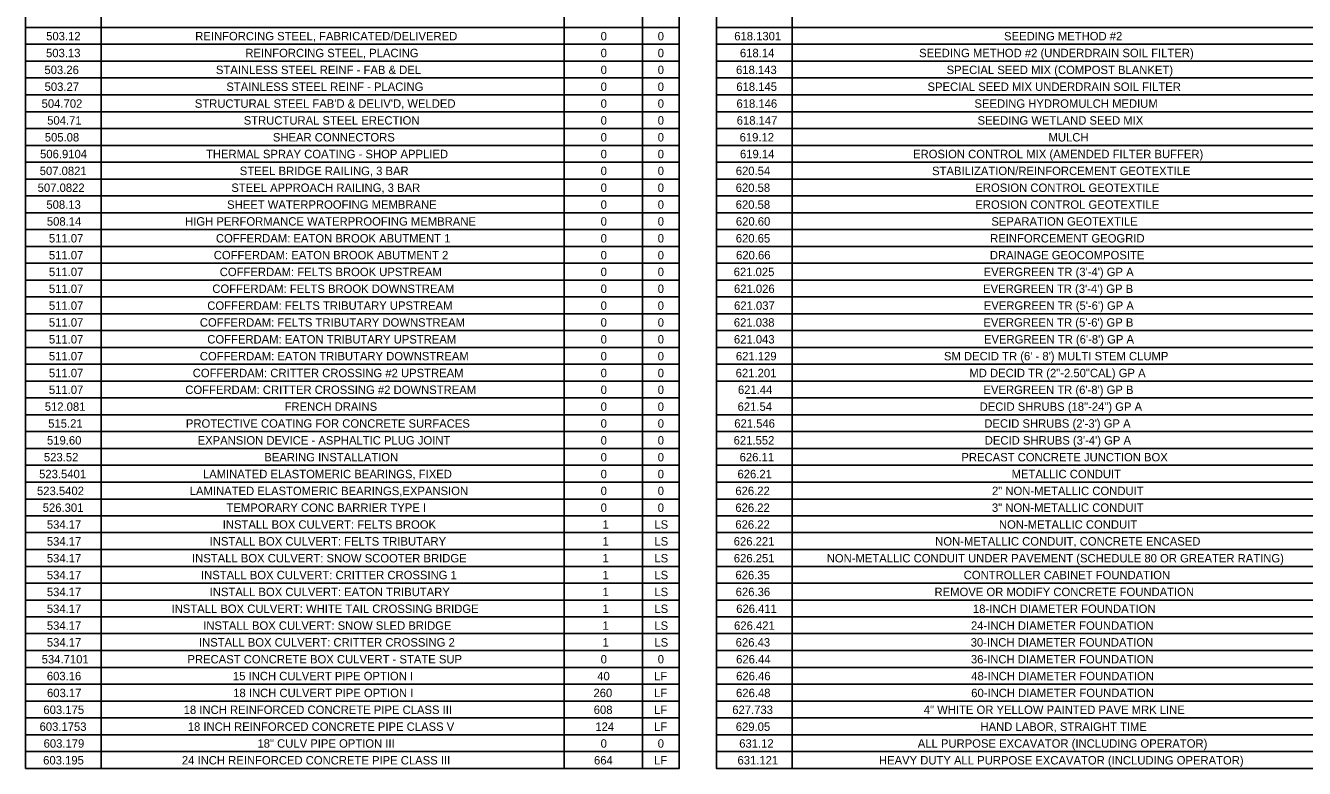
# Model space of a CAD drawing. Extents: x -18.7 to 5.6, y -2.7 to 4.
# Drawn here: x 3.137 to 4.632, y 0.019 to 0.887 of the extents above; entities that cross this region are included whole.
import ezdxf

# ---------------------------------------------------------------- set-up
doc = ezdxf.new("R2010")
doc.units = 0
doc.layers.add('ANNOTATION', color=7, linetype='Continuous')
doc.layers.add('BORDER', color=7, linetype='Continuous')

msp = doc.modelspace()

# ---------------------------------------------------------------- linework, layer by layer
at = {"layer": 'BORDER'}
for p, q in [((3.2255, 1.7315), (3.2255, 0.0189)), ((3.7669, 1.7315), (3.7669, 0.0189)), ((3.8583, 1.7315), (3.8583, 0.0189)), ((4.0334, 1.7315), (4.0334, 0.0189)), ((3.1369, 0.885), (3.9012, 0.885)), ((3.9448, 0.885), (4.8091, 0.885)), ((3.1369, 0.8654), (3.9012, 0.8654)), ((3.9448, 0.8654), (4.8091, 0.8654)), ((3.1369, 0.8457), (3.9012, 0.8457)), ((3.9448, 0.8457), (4.8091, 0.8457)), ((3.1369, 0.826), (3.9012, 0.826)), ((3.9448, 0.826), (4.8091, 0.826)), ((3.1369, 0.8063), (3.9012, 0.8063)), ((3.9448, 0.8063), (4.8091, 0.8063)), ((3.1369, 0.7866), (3.9012, 0.7866)), ((3.9448, 0.7866), (4.8091, 0.7866)), ((3.1369, 0.7669), (3.9012, 0.7669)), ((3.9448, 0.7669), (4.8091, 0.7669)), ((3.1369, 0.7472), (3.9012, 0.7472)), ((3.9448, 0.7472), (4.8091, 0.7472)), ((3.1369, 0.7276), (3.9012, 0.7276)), ((3.9448, 0.7276), (4.8091, 0.7276)), ((3.1369, 0.7079), (3.9012, 0.7079)), ((3.9448, 0.7079), (4.8091, 0.7079)), ((3.1369, 0.6882), (3.9012, 0.6882)), ((3.9448, 0.6882), (4.8091, 0.6882)), ((3.1369, 0.6685), (3.9012, 0.6685)), ((3.9448, 0.6685), (4.8091, 0.6685)), ((3.1369, 0.6488), (3.9012, 0.6488)), ((3.9448, 0.6488), (4.8091, 0.6488)), ((3.1369, 0.6291), (3.9012, 0.6291)), ((3.9448, 0.6291), (4.8091, 0.6291)), ((3.1369, 0.6094), (3.9012, 0.6094)), ((3.9448, 0.6094), (4.8091, 0.6094)), ((3.1369, 0.5898), (3.9012, 0.5898)), ((3.9448, 0.5898), (4.8091, 0.5898)), ((3.1369, 0.5701), (3.9012, 0.5701)), ((3.9448, 0.5701), (4.8091, 0.5701)), ((3.1369, 0.5504), (3.9012, 0.5504)), ((3.9448, 0.5504), (4.8091, 0.5504)), ((3.1369, 0.5307), (3.9012, 0.5307)), ((3.9448, 0.5307), (4.8091, 0.5307)), ((3.1369, 0.511), (3.9012, 0.511)), ((3.9448, 0.511), (4.8091, 0.511)), ((3.1369, 0.4913), (3.9012, 0.4913)), ((3.9448, 0.4913), (4.8091, 0.4913)), ((3.1369, 0.4716), (3.9012, 0.4716)), ((3.9448, 0.4716), (4.8091, 0.4716)), ((3.1369, 0.452), (3.9012, 0.452)), ((3.9799, 0.452), (4.8091, 0.452)), ((3.1369, 0.4323), (3.9012, 0.4323)), ((3.9448, 0.4323), (4.8091, 0.4323)), ((3.1369, 0.4126), (3.9012, 0.4126)), ((3.9448, 0.4126), (4.8091, 0.4126)), ((3.1369, 0.3929), (3.9012, 0.3929)), ((3.9448, 0.3929), (4.8091, 0.3929)), ((3.1369, 0.3732), (3.9012, 0.3732)), ((3.9448, 0.3732), (4.8091, 0.3732)), ((3.1369, 0.3535), (3.9012, 0.3535)), ((3.9448, 0.3535), (4.8091, 0.3535)), ((3.1369, 0.3338), (3.9012, 0.3338)), ((3.9448, 0.3338), (4.8091, 0.3338)), ((3.1369, 0.3142), (3.9012, 0.3142)), ((3.9448, 0.3142), (4.8091, 0.3142)), ((3.1369, 0.2945), (3.9012, 0.2945)), ((3.9448, 0.2945), (4.8091, 0.2945)), ((3.1369, 0.2748), (3.9012, 0.2748)), ((3.9448, 0.2748), (4.8091, 0.2748)), ((3.1369, 0.2551), (3.9012, 0.2551)), ((3.9448, 0.2551), (4.8091, 0.2551)), ((3.1369, 0.2354), (3.9012, 0.2354)), ((3.9448, 0.2354), (4.8091, 0.2354)), ((3.1369, 0.2157), (3.9012, 0.2157)), ((3.9448, 0.2157), (4.8091, 0.2157)), ((3.1369, 0.196), (3.9012, 0.196)), ((3.9448, 0.196), (4.8091, 0.196)), ((3.1369, 0.1764), (3.9012, 0.1764)), ((3.9448, 0.1764), (4.8091, 0.1764)), ((3.1369, 0.1567), (3.9012, 0.1567)), ((3.9448, 0.1567), (4.8091, 0.1567)), ((3.1369, 0.137), (3.9012, 0.137)), ((3.9448, 0.137), (4.8091, 0.137)), ((3.1369, 0.1173), (3.9012, 0.1173)), ((3.9448, 0.1173), (4.8091, 0.1173)), ((3.1369, 0.0976), (3.9012, 0.0976)), ((3.9448, 0.0976), (4.8091, 0.0976)), ((3.1369, 0.0779), (3.9012, 0.0779)), ((3.9448, 0.0779), (4.8091, 0.0779)), ((3.1369, 0.0582), (3.9012, 0.0582)), ((3.9448, 0.0582), (4.8091, 0.0582)), ((3.1369, 0.0386), (3.9012, 0.0386)), ((3.9448, 0.0386), (4.8091, 0.0386)), ((3.1369, 0.0189), (3.9012, 0.0189))]:
    msp.add_line(p, q, dxfattribs=at)
for points in [[(3.1369, 1.7512), (3.9012, 1.7512), (3.9012, 0.0189), (3.1369, 0.0189)], [(3.9448, 1.7512), (4.8091, 1.7512), (4.8091, 0.0189), (3.9448, 0.0189)]]:
    msp.add_lwpolyline(points, close=True, dxfattribs=at)

# ---------------------------------------------------------------- texts
at = {"layer": 'ANNOTATION'}
for s, height, p in [('503.12', 0.00984, (3.161, 0.87)), ('REINFORCING STEEL, FABRICATED/DELIVERED', 0.009843, (3.3353, 0.87)), ('0', 0.00984, (3.8094, 0.87)), ('0', 0.00984, (3.8761, 0.87)), ('618.1301', 0.00984, (3.9656, 0.87)), ('SEEDING METHOD #2', 0.009843, (4.2811, 0.87)), ('503.13', 0.00984, (3.1609, 0.8503)), ('REINFORCING STEEL, PLACING', 0.009843, (3.3939, 0.8503)), ('0', 0.00984, (3.8094, 0.8503)), ('0', 0.00984, (3.8761, 0.8503)), ('618.14', 0.00984, (3.9722, 0.8503)), ('SEEDING METHOD #2 (UNDERDRAIN SOIL FILTER)', 0.009843, (4.1818, 0.8503)), ('503.26', 0.00984, (3.159, 0.8306)), ('STAINLESS STEEL REINF - FAB & DEL', 0.009843, (3.3595, 0.8306)), ('0', 0.00984, (3.8094, 0.8306)), ('0', 0.00984, (3.8761, 0.8306)), ('618.143', 0.00984, (3.9677, 0.8306)), ('SPECIAL SEED MIX (COMPOST BLANKET)', 0.009843, (4.2139, 0.8306)), ('503.27', 0.00984, (3.1592, 0.8109)), ('STAINLESS STEEL REINF - PLACING', 0.009843, (3.3717, 0.8109)), ('0', 0.00984, (3.8094, 0.8109)), ('0', 0.00984, (3.8761, 0.8109)), ('618.145', 0.00984, (3.968, 0.8109)), ('SPECIAL SEED MIX UNDERDRAIN SOIL FILTER', 0.009843, (4.1916, 0.8109)), ('504.702', 0.00984, (3.1557, 0.7912)), ("STRUCTURAL STEEL FAB'D & DELIV'D, WELDED", 0.009843, (3.3348, 0.7912)), ('0', 0.00984, (3.8094, 0.7912)), ('0', 0.00984, (3.8761, 0.7912)), ('618.146', 0.00984, (3.9682, 0.7912)), ('SEEDING HYDROMULCH MEDIUM', 0.009843, (4.2465, 0.7912)), ('504.71', 0.00984, (3.1622, 0.7715)), ('STRUCTURAL STEEL ERECTION', 0.009843, (3.392, 0.7715)), ('0', 0.00984, (3.8094, 0.7715)), ('0', 0.00984, (3.8761, 0.7715)), ('618.147', 0.00984, (3.9685, 0.7715)), ('SEEDING WETLAND SEED MIX', 0.009843, (4.2501, 0.7715)), ('505.08', 0.00984, (3.1594, 0.7518)), ('SHEAR CONNECTORS', 0.009843, (3.4261, 0.7518)), ('0', 0.00984, (3.8094, 0.7518)), ('0', 0.00984, (3.8761, 0.7518)), ('619.12', 0.00984, (3.9719, 0.7518)), ('MULCH', 0.00984, (4.3331, 0.7518)), ('506.9104', 0.00984, (3.1539, 0.7322)), ('THERMAL SPRAY COATING - SHOP APPLIED', 0.009843, (3.3479, 0.7322)), ('0', 0.00984, (3.8094, 0.7322)), ('0', 0.00984, (3.8761, 0.7322)), ('619.14', 0.00984, (3.9723, 0.7322)), ('EROSION CONTROL MIX (AMENDED FILTER BUFFER)', 0.009843, (4.1747, 0.7322)), ('507.0821', 0.00984, (3.1535, 0.7125)), ('STEEL BRIDGE RAILING, 3 BAR', 0.009843, (3.3874, 0.7125)), ('0', 0.00984, (3.8094, 0.7125)), ('0', 0.00984, (3.8761, 0.7125)), ('620.54', 0.00984, (3.9674, 0.7125)), ('STABILIZATION/REINFORCEMENT GEOTEXTILE', 0.009843, (4.1969, 0.7125)), ('507.0822', 0.00984, (3.1511, 0.6928)), ('STEEL APPROACH RAILING, 3 BAR', 0.009843, (3.3775, 0.6928)), ('0', 0.00984, (3.8094, 0.6928)), ('0', 0.00984, (3.8761, 0.6928)), ('620.58', 0.00984, (3.9673, 0.6928)), ('EROSION CONTROL GEOTEXTILE', 0.009843, (4.2475, 0.6928)), ('508.13', 0.00984, (3.1613, 0.6731)), ('SHEET WATERPROOFING MEMBRANE', 0.009843, (3.3726, 0.6731)), ('0', 0.00984, (3.8094, 0.6731)), ('0', 0.00984, (3.8761, 0.6731)), ('620.58', 0.00984, (3.9673, 0.6731)), ('EROSION CONTROL GEOTEXTILE', 0.009843, (4.2475, 0.6731)), ('508.14', 0.00984, (3.1618, 0.6534)), ('HIGH PERFORMANCE WATERPROOFING MEMBRANE', 0.009843, (3.3235, 0.6534)), ('0', 0.00984, (3.8094, 0.6534)), ('0', 0.00984, (3.8761, 0.6534)), ('620.60', 0.00984, (3.9675, 0.6534)), ('SEPARATION GEOTEXTILE', 0.009843, (4.2662, 0.6534)), ('511.07', 0.00984, (3.1642, 0.6337)), ('COFFERDAM: EATON BROOK ABUTMENT 1', 0.009843, (3.3595, 0.6337)), ('0', 0.00984, (3.8094, 0.6337)), ('0', 0.00984, (3.8761, 0.6337)), ('620.65', 0.00984, (3.9674, 0.6337)), ('REINFORCEMENT GEOGRID', 0.009843, (4.2648, 0.6337)), ('511.07', 0.00984, (3.1642, 0.614)), ('COFFERDAM: EATON BROOK ABUTMENT 2', 0.009843, (3.357, 0.614)), ('0', 0.00984, (3.8094, 0.614)), ('0', 0.00984, (3.8761, 0.614)), ('620.66', 0.00984, (3.9677, 0.614)), ('DRAINAGE GEOCOMPOSITE', 0.009843, (4.2645, 0.614)), ('511.07', 0.00984, (3.1642, 0.5944)), ('COFFERDAM: FELTS BROOK UPSTREAM', 0.009843, (3.364, 0.5944)), ('0', 0.00984, (3.8094, 0.5944)), ('0', 0.00984, (3.8761, 0.5944)), ('621.025', 0.00984, (3.965, 0.5944)), ("EVERGREEN TR (3'-4') GP A", 0.009843, (4.2572, 0.5944)), ('511.07', 0.00984, (3.1642, 0.5747)), ('COFFERDAM: FELTS BROOK DOWNSTREAM', 0.009843, (3.3553, 0.5747)), ('0', 0.00984, (3.8094, 0.5747)), ('0', 0.00984, (3.8761, 0.5747)), ('621.026', 0.00984, (3.9653, 0.5747)), ("EVERGREEN TR (3'-4') GP B", 0.009843, (4.2566, 0.5747)), ('511.07', 0.00984, (3.1642, 0.555)), ('COFFERDAM: FELTS TRIBUTARY UPSTREAM', 0.009843, (3.3494, 0.555)), ('0', 0.00984, (3.8094, 0.555)), ('0', 0.00984, (3.8761, 0.555)), ('621.037', 0.00984, (3.9654, 0.555)), ("EVERGREEN TR (5'-6') GP A", 0.009843, (4.2574, 0.555)), ('511.07', 0.00984, (3.1642, 0.5353)), ('COFFERDAM: FELTS TRIBUTARY DOWNSTREAM', 0.009843, (3.3407, 0.5353)), ('0', 0.00984, (3.8094, 0.5353)), ('0', 0.00984, (3.8761, 0.5353)), ('621.038', 0.00984, (3.9651, 0.5353)), ("EVERGREEN TR (5'-6') GP B", 0.009843, (4.2569, 0.5353)), ('511.07', 0.00984, (3.1642, 0.5156)), ('COFFERDAM: EATON TRIBUTARY UPSTREAM', 0.009843, (3.3494, 0.5156)), ('0', 0.00984, (3.8094, 0.5156)), ('0', 0.00984, (3.8761, 0.5156)), ('621.043', 0.00984, (3.9652, 0.5156)), ("EVERGREEN TR (6'-8') GP A", 0.009843, (4.2576, 0.5156)), ('511.07', 0.00984, (3.1642, 0.4959)), ('COFFERDAM: EATON TRIBUTARY DOWNSTREAM', 0.009843, (3.3407, 0.4959)), ('0', 0.00984, (3.8094, 0.4959)), ('0', 0.00984, (3.8761, 0.4959)), ('621.129', 0.00984, (3.9675, 0.4959)), ("SM DECID TR (6' - 8') MULTI STEM CLUMP", 0.009843, (4.2108, 0.4959)), ('511.07', 0.00984, (3.1642, 0.4762)), ('COFFERDAM: CRITTER CROSSING #2 UPSTREAM', 0.009843, (3.3324, 0.4762)), ('0', 0.00984, (3.8094, 0.4762)), ('0', 0.00984, (3.8761, 0.4762)), ('621.201', 0.00984, (3.9673, 0.4762)), ('MD DECID TR (2"-2.50"CAL) GP A', 0.009843, (4.2405, 0.4762)), ('511.07', 0.00984, (3.1642, 0.4566)), ('COFFERDAM: CRITTER CROSSING #2 DOWNSTREAM', 0.009843, (3.3237, 0.4566)), ('0', 0.00984, (3.8094, 0.4566)), ('0', 0.00984, (3.8761, 0.4566)), ('621.44', 0.00984, (3.9699, 0.4566)), ("EVERGREEN TR (6'-8') GP B", 0.009843, (4.257, 0.4566)), ('512.081', 0.00984, (3.1594, 0.4369)), ('FRENCH DRAINS', 0.009843, (3.4398, 0.4369)), ('0', 0.00984, (3.8094, 0.4369)), ('0', 0.00984, (3.8761, 0.4369)), ('621.54', 0.00984, (3.9695, 0.4369)), ('DECID SHRUBS (18"-24") GP A', 0.009843, (4.2525, 0.4369)), ('515.21', 0.00984, (3.1634, 0.4172)), ('PROTECTIVE COATING FOR CONCRETE SURFACES', 0.009843, (3.3244, 0.4172)), ('0', 0.00984, (3.8094, 0.4172)), ('0', 0.00984, (3.8761, 0.4172)), ('621.546', 0.00984, (3.9656, 0.4172)), ("DECID SHRUBS (2'-3') GP A", 0.009843, (4.258, 0.4172)), ('519.60', 0.00984, (3.162, 0.3975)), ('EXPANSION DEVICE - ASPHALTIC PLUG JOINT', 0.009843, (3.3381, 0.3975)), ('0', 0.00984, (3.8094, 0.3975)), ('0', 0.00984, (3.8761, 0.3975)), ('621.552', 0.00984, (3.9649, 0.3975)), ("DECID SHRUBS (3'-4') GP A", 0.009843, (4.2585, 0.3975)), ('523.52', 0.00984, (3.1584, 0.3778)), ('BEARING INSTALLATION', 0.009843, (3.4161, 0.3778)), ('0', 0.00984, (3.8094, 0.3778)), ('0', 0.00984, (3.8761, 0.3778)), ('626.11', 0.00984, (3.9719, 0.3778)), ('PRECAST CONCRETE JUNCTION BOX', 0.009843, (4.2312, 0.3778)), ('523.5401', 0.00984, (3.1528, 0.3581)), ('LAMINATED ELASTOMERIC BEARINGS, FIXED', 0.009843, (3.3443, 0.3581)), ('0', 0.00984, (3.8094, 0.3581)), ('0', 0.00984, (3.8761, 0.3581)), ('626.21', 0.00984, (3.9694, 0.3581)), ('METALLIC CONDUIT', 0.009843, (4.2899, 0.3581)), ('523.5402', 0.00984, (3.1503, 0.3384)), ('LAMINATED ELASTOMERIC BEARINGS,EXPANSION', 0.009843, (3.3289, 0.3384)), ('0', 0.00984, (3.8094, 0.3384)), ('0', 0.00984, (3.8761, 0.3384)), ('626.22', 0.00984, (3.9669, 0.3384)), ('2" NON-METALLIC CONDUIT', 0.009843, (4.267, 0.3384)), ('526.301', 0.00984, (3.157, 0.3188)), ('TEMPORARY CONC BARRIER TYPE I', 0.009843, (3.3719, 0.3188)), ('0', 0.00984, (3.8094, 0.3188)), ('0', 0.00984, (3.8761, 0.3188)), ('626.22', 0.00984, (3.9669, 0.3188)), ('3" NON-METALLIC CONDUIT', 0.009843, (4.2669, 0.3188)), ('534.17', 0.00984, (3.1618, 0.2991)), ('INSTALL BOX CULVERT: FELTS BROOK', 0.009843, (3.3675, 0.2991)), ('1', 0.00984, (3.8115, 0.2991)), ('LS', 0.00984, (3.8722, 0.2991)), ('626.22', 0.00984, (3.9669, 0.2991)), ('NON-METALLIC CONDUIT', 0.009843, (4.2751, 0.2991)), ('534.17', 0.00984, (3.1618, 0.2794)), ('INSTALL BOX CULVERT: FELTS TRIBUTARY', 0.009843, (3.3522, 0.2794)), ('1', 0.00984, (3.8115, 0.2794)), ('LS', 0.00984, (3.8722, 0.2794)), ('626.221', 0.00984, (3.965, 0.2794)), ('NON-METALLIC CONDUIT, CONCRETE ENCASED', 0.009843, (4.2006, 0.2794)), ('534.17', 0.00984, (3.1618, 0.2597)), ('INSTALL BOX CULVERT: SNOW SCOOTER BRIDGE', 0.009843, (3.3316, 0.2597)), ('1', 0.00984, (3.8115, 0.2597)), ('LS', 0.00984, (3.8722, 0.2597)), ('626.251', 0.00984, (3.9651, 0.2597)), ('NON-METALLIC CONDUIT UNDER PAVEMENT (SCHEDULE 80 OR GREATER RATING)', 0.009843, (4.0737, 0.2597)), ('534.17', 0.00984, (3.1618, 0.24)), ('INSTALL BOX CULVERT: CRITTER CROSSING 1', 0.009843, (3.3421, 0.24)), ('1', 0.00984, (3.8115, 0.24)), ('LS', 0.00984, (3.8722, 0.24)), ('626.35', 0.00984, (3.967, 0.24)), ('CONTROLLER CABINET FOUNDATION', 0.009843, (4.2339, 0.24)), ('534.17', 0.00984, (3.1618, 0.2203)), ('INSTALL BOX CULVERT: EATON TRIBUTARY', 0.009843, (3.3522, 0.2203)), ('1', 0.00984, (3.8115, 0.2203)), ('LS', 0.00984, (3.8722, 0.2203)), ('626.36', 0.00984, (3.9673, 0.2203)), ('REMOVE OR MODIFY CONCRETE FOUNDATION', 0.009843, (4.1998, 0.2203)), ('534.17', 0.00984, (3.1618, 0.2006)), ('INSTALL BOX CULVERT: WHITE TAIL CROSSING BRIDGE', 0.009843, (3.3076, 0.2006)), ('1', 0.00984, (3.8115, 0.2006)), ('LS', 0.00984, (3.8722, 0.2006)), ('626.411', 0.00984, (3.9679, 0.2006)), ('18-INCH DIAMETER FOUNDATION', 0.009843, (4.2447, 0.2006)), ('534.17', 0.00984, (3.1618, 0.1809)), ('INSTALL BOX CULVERT: SNOW SLED BRIDGE', 0.009843, (3.3446, 0.1809)), ('1', 0.00984, (3.8115, 0.1809)), ('LS', 0.00984, (3.8722, 0.1809)), ('626.421', 0.00984, (3.9654, 0.1809)), ('24-INCH DIAMETER FOUNDATION', 0.009843, (4.2424, 0.1809)), ('534.17', 0.00984, (3.1618, 0.1613)), ('INSTALL BOX CULVERT: CRITTER CROSSING 2', 0.009843, (3.3397, 0.1613)), ('1', 0.00984, (3.8115, 0.1613)), ('LS', 0.00984, (3.8722, 0.1613)), ('626.43', 0.00984, (3.9673, 0.1613)), ('30-INCH DIAMETER FOUNDATION', 0.009843, (4.2421, 0.1613)), ('534.7101', 0.00984, (3.1558, 0.1416)), ('PRECAST CONCRETE BOX CULVERT - STATE SUP', 0.009843, (3.3262, 0.1416)), ('0', 0.00984, (3.8094, 0.1416)), ('0', 0.00984, (3.8761, 0.1416)), ('626.44', 0.00984, (3.9678, 0.1416)), ('36-INCH DIAMETER FOUNDATION', 0.009843, (4.2423, 0.1416)), ('603.16', 0.00984, (3.1618, 0.1219)), ('15 INCH CULVERT PIPE OPTION I', 0.009843, (3.3794, 0.1219)), ('40', 0.00984, (3.8054, 0.1219)), ('LF', 0.00984, (3.8718, 0.1219)), ('626.46', 0.00984, (3.9678, 0.1219)), ('48-INCH DIAMETER FOUNDATION', 0.009843, (4.2427, 0.1219)), ('603.17', 0.00984, (3.162, 0.1022)), ('18 INCH CULVERT PIPE OPTION I', 0.009843, (3.3797, 0.1022)), ('260', 0.00984, (3.801, 0.1022)), ('LF', 0.00984, (3.8718, 0.1022)), ('626.48', 0.00984, (3.9677, 0.1022)), ('60-INCH DIAMETER FOUNDATION', 0.009843, (4.2427, 0.1022)), ('603.175', 0.00984, (3.1578, 0.0825)), ('18 INCH REINFORCED CONCRETE PIPE CLASS III', 0.009843, (3.3218, 0.0825)), ('608', 0.00984, (3.8013, 0.0825)), ('LF', 0.00984, (3.8718, 0.0825)), ('627.733', 0.00984, (3.9633, 0.0825)), ('4" WHITE OR YELLOW PAINTED PAVE MRK LINE', 0.009843, (4.1872, 0.0825)), ('603.1753', 0.00984, (3.1533, 0.0628)), ('18 INCH REINFORCED CONCRETE PIPE CLASS V', 0.009843, (3.3266, 0.0628)), ('124', 0.00984, (3.8032, 0.0628)), ('LF', 0.00984, (3.8718, 0.0628)), ('629.05', 0.00984, (3.9674, 0.0628)), ('HAND LABOR, STRAIGHT TIME', 0.009843, (4.2535, 0.0628)), ('603.179', 0.00984, (3.158, 0.0431)), ('18" CULV PIPE OPTION III', 0.009843, (3.4081, 0.0431)), ('0', 0.00984, (3.8094, 0.0431)), ('0', 0.00984, (3.8761, 0.0431)), ('631.12', 0.00984, (3.9714, 0.0431)), ('ALL PURPOSE EXCAVATOR (INCLUDING OPERATOR)', 0.009843, (4.1802, 0.0431)), ('603.195', 0.00984, (3.1575, 0.0235)), ('24 INCH REINFORCED CONCRETE PIPE CLASS III', 0.009843, (3.3197, 0.0235)), ('664', 0.00984, (3.8016, 0.0235)), ('LF', 0.00984, (3.8718, 0.0235)), ('631.121', 0.00984, (3.9694, 0.0235)), ('HEAVY DUTY ALL PURPOSE EXCAVATOR (INCLUDING OPERATOR)', 0.009843, (4.1348, 0.0235))]:
    msp.add_text(s, height=height, dxfattribs=at).set_placement(p)

doc.saveas('drawing.dxf')
